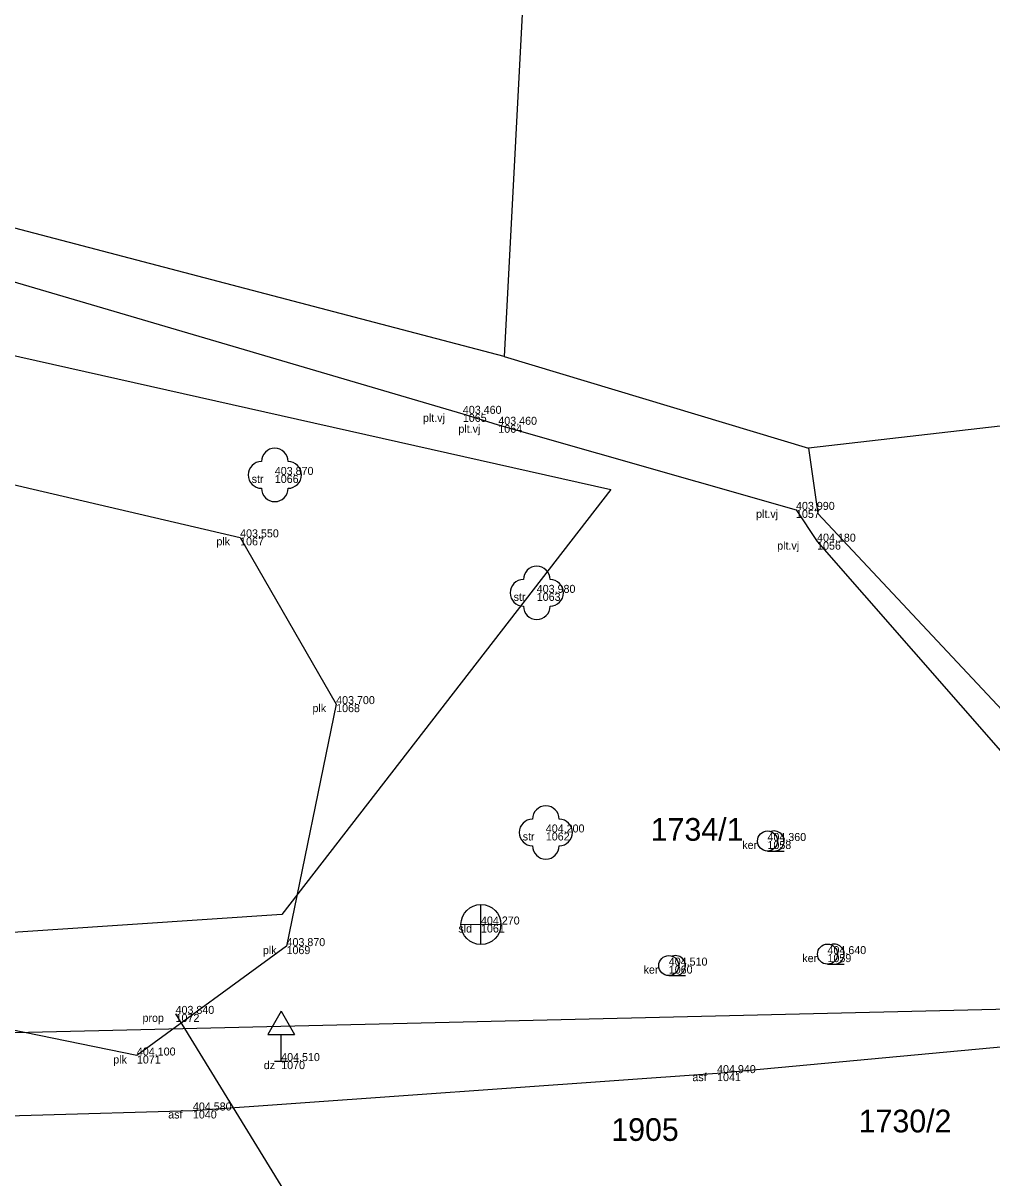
# Model space of a CAD drawing. Extents: x -747792 to -745414, y -1093712 to -1091463.
# Drawn here: x -746998.41 to -746962.09, y -1092159.04 to -1092115.75 of the extents above; entities that cross this region are included whole.
import ezdxf

# ---------------------------------------------------------------- set-up
doc = ezdxf.new("R2010")
doc.units = 0
for name, color, linetype in [('Doplňkové značky', 7, 'Continuous'), ('Hladina', 7, 'Continuous'), ('Koleje_dopravní prvky', 7, 'Continuous'), ('Nezařazené objekty', 7, 'Continuous'), ('Nivelační značky_hrany', 7, 'Continuous'), ('Názvy obcí_ulic', 7, 'Continuous'), ('Pracovní_bod JDTM STC_VC - výška', 7, 'Continuous'), ('Pracovní_bod PPBP - výška', 7, 'Continuous'), ('Pracovní_bod PPBP - číslo', 7, 'Continuous'), ('Pracovní_bod ZPBP', 7, 'Continuous'), ('Rozhraní ploch', 7, 'Continuous'), ('Stromy_porost', 7, 'Continuous'), ('Výškopis', 7, 'Continuous'), ('Čísla popisná_parcelní', 7, 'Continuous')]:
    doc.layers.add(name, color=color, linetype=linetype)

msp = doc.modelspace()

# ---------------------------------------------------------------- linework, layer by layer
at = {"layer": 'Hladina'}
for p, q in [((-746981.92, -1092130.4), (-746981.92, -1092130.4)), ((-746980.59, -1092130.81), (-746980.59, -1092130.81)), ((-746988.97, -1092132.69), (-746988.97, -1092132.69)), ((-746969.43, -1092134), (-746969.43, -1092134)), ((-746990.27, -1092135.03), (-746990.27, -1092135.03)), ((-746968.64, -1092135.19), (-746968.64, -1092135.19)), ((-746979.15, -1092137.11), (-746979.15, -1092137.11)), ((-746986.67, -1092141.28), (-746986.67, -1092141.28)), ((-746978.81, -1092146.09), (-746978.81, -1092146.09)), ((-746970.5, -1092146.41), (-746970.5, -1092146.41)), ((-746981.24, -1092149.54), (-746981.24, -1092149.54)), ((-746988.53, -1092150.35), (-746988.53, -1092150.35)), ((-746968.25, -1092150.65), (-746968.25, -1092150.65)), ((-746974.2, -1092151.08), (-746974.2, -1092151.08)), ((-746992.69, -1092152.89), (-746992.69, -1092152.89)), ((-746994.14, -1092154.45), (-746994.14, -1092154.45)), ((-746988.73, -1092154.66), (-746988.73, -1092154.66)), ((-746972.39, -1092155.11), (-746972.39, -1092155.11)), ((-746992.04, -1092156.51), (-746992.04, -1092156.51))]:
    msp.add_line(p, q, dxfattribs=at)
at = {"layer": 'Nezařazené objekty'}
for points in [[(-747013.41, -1092121.14), (-746981.92, -1092130.4)], [(-747028.72, -1092136.62), (-747030.15, -1092136.4), (-747027.66, -1092131.51), (-747022.12, -1092127.6), (-746990.27, -1092135.03), (-746986.67, -1092141.28), (-746988.53, -1092150.35), (-746994.14, -1092154.45), (-747026.74, -1092147.78), (-747030.92, -1092141.49), (-747029.75, -1092141.75)], [(-746980.59, -1092130.81), (-746969.43, -1092134)], [(-746968.64, -1092135.19), (-746959.65, -1092145.44), (-746950.72, -1092152.88), (-746936.38, -1092150.08), (-746920.79, -1092143.84), (-746911.39, -1092138.35)]]:
    msp.add_lwpolyline(points, dxfattribs=at)
at = {"layer": 'Nivelační značky_hrany'}
msp.add_lwpolyline([(-747031.47, -1092121.46), (-747034.37, -1092131.06), (-747035.22, -1092135.4), (-747034.61, -1092139.48), (-747032.02, -1092145.03), (-747030.43, -1092149.46), (-747026.22, -1092153.71), (-747022.05, -1092156), (-747017.81, -1092156.72), (-747004.18, -1092156.86), (-746992.04, -1092156.51), (-746972.39, -1092155.11), (-746956.38, -1092153.63), (-746948.42, -1092153.01), (-746939.51, -1092151.24), (-746935.43, -1092150.07), (-746925.27, -1092146.18), (-746920.51, -1092144.15), (-746912.95, -1092141.06), (-746908.39, -1092136.61)], dxfattribs=at)
at = {"layer": 'Názvy obcí_ulic'}
for p, q in [((-746988.73, -1092152.794), (-746989.23, -1092153.66)), ((-746988.73, -1092152.794), (-746988.23, -1092153.66)), ((-746989.23, -1092153.66), (-746988.23, -1092153.66)), ((-746988.73, -1092154.66), (-746988.73, -1092153.66)), ((-746988.98, -1092154.66), (-746988.48, -1092154.66))]:
    msp.add_line(p, q, dxfattribs=at)
at = {"layer": 'Pracovní_bod JDTM STC_VC - výška'}
for centre in [(-746988.97, -1092132.69), (-746979.15, -1092137.11), (-746978.81, -1092146.09)]:
    msp.add_circle(centre, 0.0005, dxfattribs=at)
for centre, start, end in [((-746988.97, -1092132.19), 0, 180), ((-746989.47, -1092132.69), 90, 270), ((-746988.47, -1092132.69), 270, 90), ((-746988.97, -1092133.19), 180, 360), ((-746979.15, -1092136.61), 0, 180), ((-746979.65, -1092137.11), 90, 270), ((-746978.65, -1092137.11), 270, 90), ((-746979.15, -1092137.61), 180, 360), ((-746978.81, -1092145.59), 0, 180), ((-746979.31, -1092146.09), 90, 270), ((-746978.31, -1092146.09), 270, 90), ((-746978.81, -1092146.59), 180, 360)]:
    msp.add_arc(centre, 0.5, start, end, dxfattribs=at)
at = {"layer": 'Pracovní_bod PPBP - výška'}
for points in [[(-746981.92, -1092130.4), (-746980.59, -1092130.81)], [(-746969.43, -1092134), (-746968.64, -1092135.19)]]:
    msp.add_lwpolyline(points, dxfattribs=at)
at = {"layer": 'Pracovní_bod PPBP - číslo'}
for p, q in [((-746970.5, -1092146.785), (-746969.875, -1092146.785)), ((-746968.25, -1092151.025), (-746967.625, -1092151.025)), ((-746974.2, -1092151.455), (-746973.575, -1092151.455))]:
    msp.add_line(p, q, dxfattribs=at)
for centre in [(-746970.5, -1092146.41), (-746968.25, -1092150.65), (-746974.2, -1092151.08)]:
    msp.add_circle(centre, 0.375, dxfattribs=at)
for centre in [(-746970.25, -1092146.41), (-746968, -1092150.65), (-746973.95, -1092151.08)]:
    msp.add_arc(centre, 0.375, 249.4944, 109.0474, dxfattribs=at)
at = {"layer": 'Pracovní_bod ZPBP'}
msp.add_lwpolyline([(-746992.69, -1092152.89), (-746982.53, -1092169.44)], dxfattribs=at)
at = {"layer": 'Stromy_porost'}
for points in [[(-746978.68, -1092096.17), (-746980.37, -1092128.25)], [(-746980.37, -1092128.25), (-747009.98, -1092120.49)], [(-747020.08, -1092123.43), (-746976.37, -1092133.24)], [(-746980.37, -1092128.25), (-746968.96, -1092131.69)], [(-746953.83, -1092129.95), (-746968.96, -1092131.69)], [(-746968.96, -1092131.69), (-746968.61, -1092134.14)], [(-746976.37, -1092133.24), (-746988.71, -1092149.17)], [(-746968.61, -1092134.14), (-746951.43, -1092152.46)], [(-746988.71, -1092149.17), (-747020.07, -1092151.26)], [(-747020.29, -1092154.1), (-746951.43, -1092152.46)]]:
    msp.add_lwpolyline(points, dxfattribs=at)
at = {"layer": 'Čísla popisná_parcelní'}
for p, q in [((-746981.241, -1092150.288), (-746981.24, -1092148.793)), ((-746980.488, -1092149.546), (-746981.988, -1092149.541))]:
    msp.add_line(p, q, dxfattribs=at)
msp.add_circle((-746981.24, -1092149.54), 0.75, dxfattribs=at)

# ---------------------------------------------------------------- texts
at = {"layer": 'Doplňkové značky'}
for s, p in [('1730/2', (-746967.08, -1092157.33)), ('1905', (-746976.355, -1092157.65))]:
    msp.add_text(s, height=0.85, dxfattribs=at).set_placement(p)
at = {"layer": 'Koleje_dopravní prvky'}
msp.add_text('1734/1', height=0.85, dxfattribs=at).set_placement((-746974.877, -1092146.4))
at = {"layer": 'Rozhraní ploch'}
for s, p in [(' plt.vj', (-746983.528, -1092130.7)), ('1065', (-746981.92, -1092130.7)), (' plt.vj', (-746982.198, -1092131.11)), ('1064', (-746980.59, -1092131.11)), (' str', (-746989.948, -1092132.99)), ('1066', (-746988.97, -1092132.99)), (' plt.vj', (-746971.038, -1092134.3)), ('1057', (-746969.43, -1092134.3)), (' plk', (-746991.269, -1092135.33)), ('1067', (-746990.27, -1092135.33)), (' plt.vj', (-746970.248, -1092135.49)), ('1056', (-746968.64, -1092135.49)), (' str', (-746980.128, -1092137.41)), ('1063', (-746979.15, -1092137.41)), (' plk', (-746987.669, -1092141.58)), ('1068', (-746986.67, -1092141.58)), (' str', (-746979.788, -1092146.39)), ('1062', (-746978.81, -1092146.39)), (' ker', (-746971.556, -1092146.71)), ('1058', (-746970.5, -1092146.71)), (' sld', (-746982.201, -1092149.84)), ('1061', (-746981.24, -1092149.84)), (' plk', (-746989.529, -1092150.65)), ('1069', (-746988.53, -1092150.65)), (' ker', (-746969.306, -1092150.95)), ('1059', (-746968.25, -1092150.95)), (' ker', (-746975.256, -1092151.38)), ('1060', (-746974.2, -1092151.38)), (' prop', (-746994.041, -1092153.19)), ('1072', (-746992.69, -1092153.19)), (' plk', (-746995.139, -1092154.75)), ('1071', (-746994.14, -1092154.75)), (' dz', (-746989.495, -1092154.96)), ('1070', (-746988.73, -1092154.96)), (' asf', (-746973.427, -1092155.41)), ('1041', (-746972.39, -1092155.41)), (' asf', (-746993.077, -1092156.81)), ('1040', (-746992.04, -1092156.81))]:
    msp.add_text(s, height=0.3, dxfattribs=at).set_placement(p)
at = {"layer": 'Výškopis'}
for s, p in [('403,460', (-746981.92, -1092130.4)), ('403,460', (-746980.59, -1092130.81)), ('403,870', (-746988.97, -1092132.69)), ('403,990', (-746969.43, -1092134)), ('403,550', (-746990.27, -1092135.03)), ('404,180', (-746968.64, -1092135.19)), ('403,980', (-746979.15, -1092137.11)), ('403,700', (-746986.67, -1092141.28)), ('404,200', (-746978.81, -1092146.09)), ('404,360', (-746970.5, -1092146.41)), ('404,270', (-746981.24, -1092149.54)), ('403,870', (-746988.53, -1092150.35)), ('404,640', (-746968.25, -1092150.65)), ('404,510', (-746974.2, -1092151.08)), ('403,840', (-746992.69, -1092152.89)), ('404,100', (-746994.14, -1092154.45)), ('404,510', (-746988.73, -1092154.66)), ('404,940', (-746972.39, -1092155.11)), ('404,580', (-746992.04, -1092156.51))]:
    msp.add_text(s, height=0.3, dxfattribs=at).set_placement(p)

doc.saveas('drawing.dxf')
